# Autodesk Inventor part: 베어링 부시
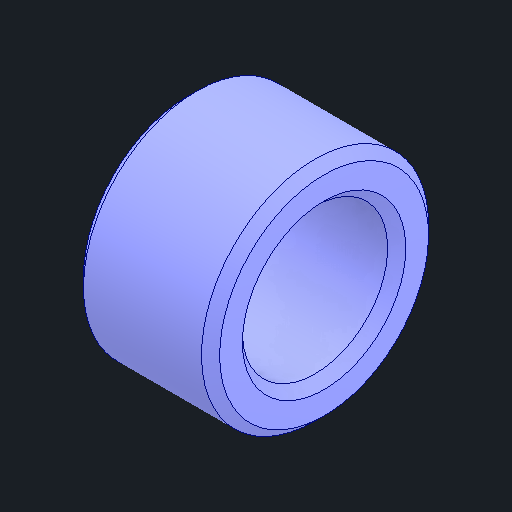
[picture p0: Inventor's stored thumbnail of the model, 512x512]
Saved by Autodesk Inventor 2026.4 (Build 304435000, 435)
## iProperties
Created: 2026-09
Part Number: 베어링 부시
Material: 강철, 연강
Document SubType Name: Modeling
Designer: user
Density: 7.86 g/cm^3
Appearance: 기본값
Author: jhkim
Sending System: Autodesk Inventor 2027
Preprocessor: ST-DEVELOPER v20.1
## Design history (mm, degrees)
feature "솔리드1"
node "솔리드2"
